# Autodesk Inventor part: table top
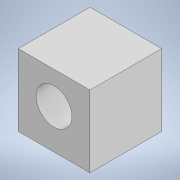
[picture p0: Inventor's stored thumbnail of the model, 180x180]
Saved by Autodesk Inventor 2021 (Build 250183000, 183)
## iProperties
Created: 2021-07
Part Number: table top
Material: Generic
Document SubType Name: Modeling
Designer: adams
Density: 1 g/cm^3
Appearance: Default
Author: adams
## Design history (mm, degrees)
sketch "Sketch1"
  geometry: 1 further point
sketch "Sketch2"
  geometry: L1 (-47.6, 43)-(54, 43); L2 (54, 43)-(54, -58.6); L3 (54, -58.6)-(-47.6, -58.6); L4 (-47.6, -58.6)-(-47.6, 43); 1 further point
  constraints: 8 end point, 2 parallel, 1 horizontal, 1 perpendicular
  dimensions: "d0" = 101.6 distance of L1.start L1.end; "d1" = 101.6 distance of L2.end L3.end (derived); "d2" = 101.6 distance of L3.end L1.start
extrude "Extrusion1" new body sketch "Sketch2" distance "d3" = 101.6; taper "d4" = 0 deg
sketch "Sketch3"
  geometry: C1 r 25.4 at (3.003, -2.585); 1 further point
  constraints: 1 centre point
  dimensions: "d5" = 50.8 diameter of C1
extrude "Extrusion2" cut sketch "Sketch3" extent not by distance; stored distance "d6" = 0; taper "d7" = 0 deg
body "Solid1"
